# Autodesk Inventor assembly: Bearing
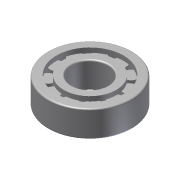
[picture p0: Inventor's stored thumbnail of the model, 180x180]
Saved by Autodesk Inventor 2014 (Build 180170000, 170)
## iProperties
Created: 2010-12
Part Number: Bearing
Document SubType Name: Assembly
Designer: Beta-8540w
ClientObjectVersion: 1
Author: Beta-8540w
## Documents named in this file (2)
- C:\Inventor 2014 Essentials\Assemblies\Chapter 09\Design Accelerators\Bearing c09-01.iam
- C:\Inventor 2014 Essentials\Content Center Files\en-US\SKF NJ\SKF NJNJ 202 EC.ipt
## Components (1 placed, 1 different names)
1. SKF NJ SKF NJNJ 202 EC:1
